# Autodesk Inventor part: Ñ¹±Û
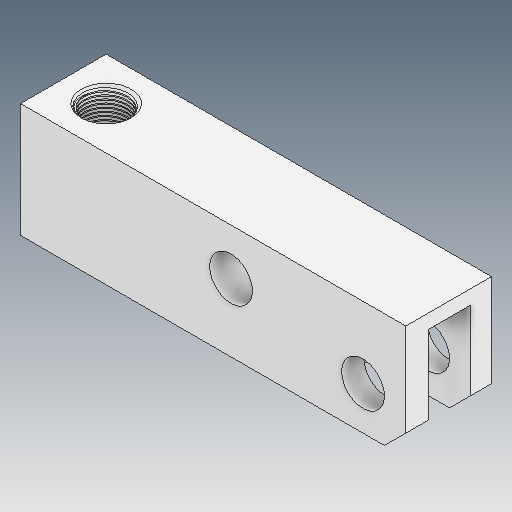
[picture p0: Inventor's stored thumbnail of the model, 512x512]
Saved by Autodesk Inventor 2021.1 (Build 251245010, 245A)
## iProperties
Created: 2021-06
Part Number: Ñ¹±Û
Material: Ogólny
Document SubType Name: Modeling
Designer: user
Density: 1 g/cm^3
Appearance: Domyślna
Author: user
Revision Number: ÈÎºÎ
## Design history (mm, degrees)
feature "ÇÐ³ý-À­Éì3"
node "Bryła1"
